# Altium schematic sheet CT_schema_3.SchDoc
size 396 x 205 mm
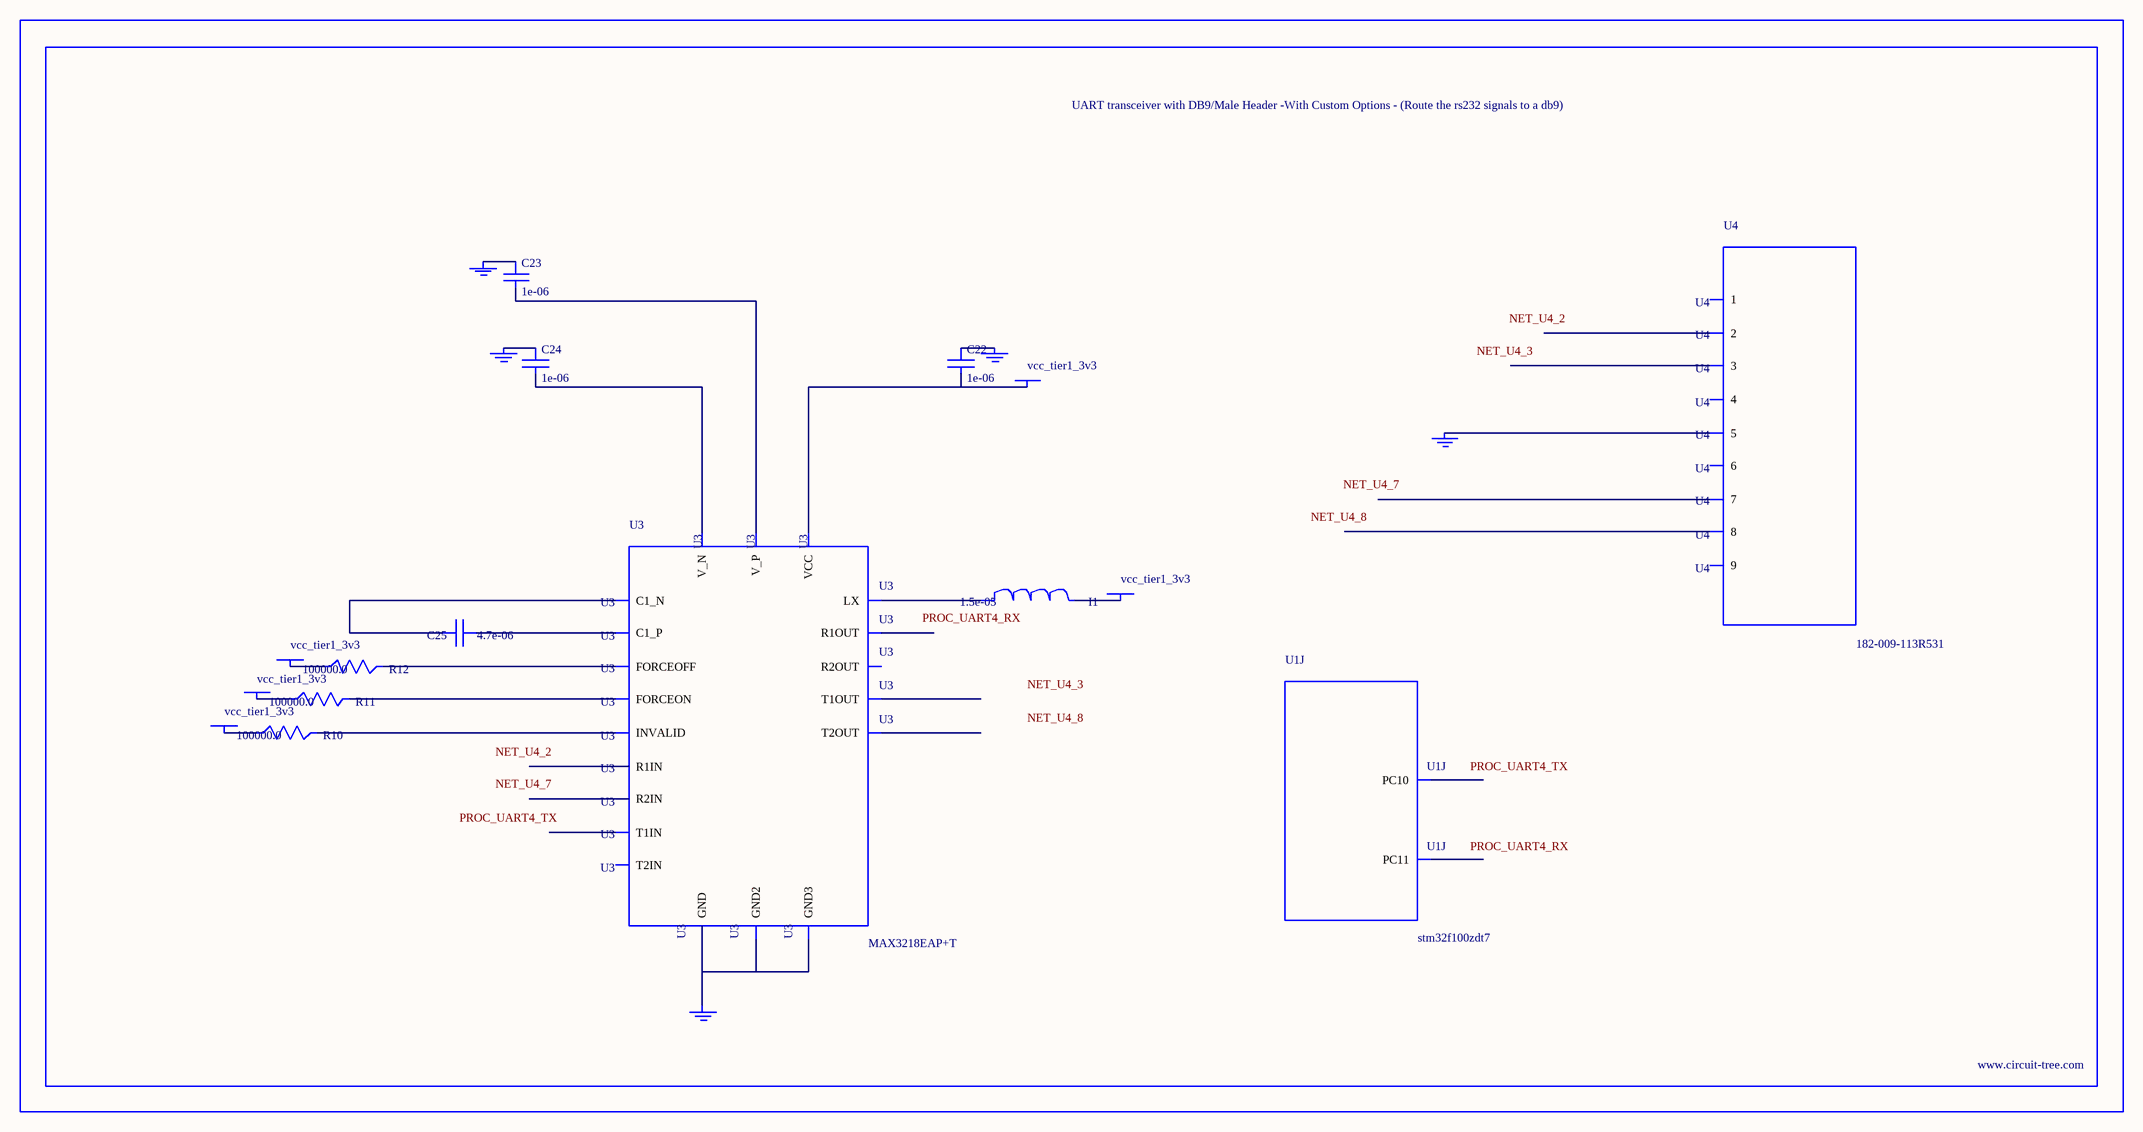
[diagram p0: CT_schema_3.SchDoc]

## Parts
BORDER2  (no value)
C22  1e-06  [C0603]
C23  1e-06  [C0603]
C24  1e-06  [C0603]
C25  4.7e-06  [C0805]
GND_INSTANCE_2_0  (no value)
GND_INSTANCE_2_1  (no value)
GND_INSTANCE_2_2  (no value)
GND_INSTANCE_2_3  (no value)
GND_INSTANCE_2_4  (no value)
I1  1.5e-05  [L1210]
POWER_INSTANCE_2_0  vcc_tier1_3v3
POWER_INSTANCE_2_1  vcc_tier1_3v3
POWER_INSTANCE_2_2  vcc_tier1_3v3
POWER_INSTANCE_2_3  vcc_tier1_3v3
POWER_INSTANCE_2_4  vcc_tier1_3v3
R10  100000.0  [R0603]
R11  100000.0  [R0603]
R12  100000.0  [R0603]
U1  stm32f100zdt7  [LQFP144]  (part J of 12)
U3  MAX3218EAP+T  [SSOP-20]
U4  182-009-113R531  [182-009-MALE]

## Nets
NetC22_1: C22.1 GND_INSTANCE_2_0.0(GND)
NetC22_2: C22.2 POWER_INSTANCE_2_4.0(PWR) U3.6(VCC)
NetC23_1: C23.1 GND_INSTANCE_2_2.0(GND)
NetC23_2: C23.2 U3.19(V_P)
NetC24_1: C24.1 GND_INSTANCE_2_1.0(GND)
NetC24_2: C24.2 U3.15(V_N)
NetC25_1: C25.1 U3.18(C1_P)
NetC25_2: C25.2 U3.16(C1_N)
NetGND_INSTANCE_2_3_0: GND_INSTANCE_2_3.0(GND) U3.5(GND) U3.17(GND2) U3.20(GND3)
NetGND_INSTANCE_2_4_0: GND_INSTANCE_2_4.0(GND) U4.5
NetI1_1: I1.1 U3.1(LX)
NetI1_2: I1.2 POWER_INSTANCE_2_0.0(PWR)
NetPOWER_INSTANCE_2_1_0: POWER_INSTANCE_2_1.0(PWR) R10.1
NetPOWER_INSTANCE_2_2_0: POWER_INSTANCE_2_2.0(PWR) R11.1
NetPOWER_INSTANCE_2_3_0: POWER_INSTANCE_2_3.0(PWR) R12.1
NetR10_2: R10.2 U3.2(INVALID)
NetR11_2: R11.2 U3.3(FORCEON)
NetR12_2: R12.2 U3.4(FORCEOFF)

Not connected (* = marked no-connect by the designer): U1 111(PC10) 112(PC11); U3 7(T1IN) 8(T2IN) 9(R1OUT) 10(R2OUT) 11(R2IN) 12(R1IN) 13(T2OUT) 14(T1OUT); U4 1 2 3 4 6 7 8 9

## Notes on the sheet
- Labels drawn without touching a wire or pin: NET_U4_2, NET_U4_3, NET_U4_7, NET_U4_8, PROC_UART4_RX, PROC_UART4_TX

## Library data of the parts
BORDER2 = BORDER_PAGE2
C22-C24 = C0603C105K3RACTU
C25 = C0805C475K4RACTU
GND_INSTANCE_2_0-GND_INSTANCE_2_4 = GND
I1 = L1210R150MDWIT
POWER_INSTANCE_2_0-POWER_INSTANCE_2_4 = PWR
R10-R12 = RC0603JR-07100KL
